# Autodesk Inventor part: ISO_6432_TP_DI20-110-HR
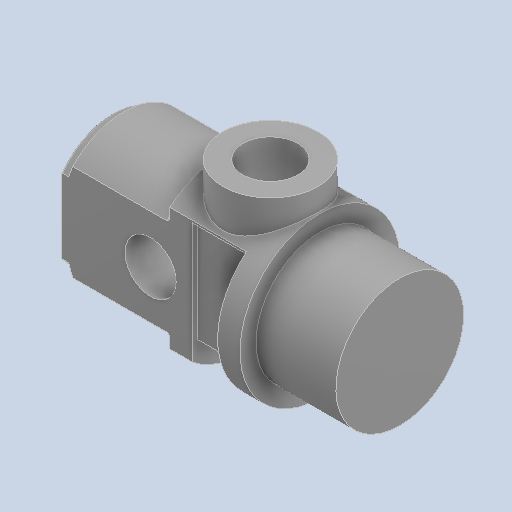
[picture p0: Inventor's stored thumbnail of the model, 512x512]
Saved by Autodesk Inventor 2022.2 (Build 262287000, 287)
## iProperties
Created: 2024-10
Part Number: ISO_6432_TP_DI20-110-HR
Material: Generico
Document SubType Name: Modeling
Designer: 18907419
Density: 1 g/cm^3
Appearance: Default
Author: 18907419
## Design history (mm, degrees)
feature "Solid1"
node "Solido1"
